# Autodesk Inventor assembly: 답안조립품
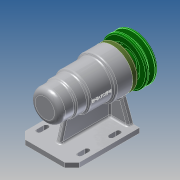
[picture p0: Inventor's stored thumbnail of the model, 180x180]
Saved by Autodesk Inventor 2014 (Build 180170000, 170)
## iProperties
Created: 2017-09
Part Number: 답안조립품
Document SubType Name: Assembly
Designer: kb542-22
Author: kb542-22
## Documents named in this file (12)
- C:\Users\kb542-22\Desktop\470907V1021\답안조립품.iam
- C:\Users\kb542-22\Desktop\470907V1021\1-본체.ipt
- C:\Users\kb542-22\Desktop\470907V1021\축.ipt
- C:\Users\kb542-22\Desktop\470907V1021\키 5 x 5 x 16.ipt
- C:\Users\kb542-22\Desktop\470907V1021\베어링 6004.ipt
- C:\Users\kb542-22\Desktop\470907V1021\V벨트풀리.ipt
- C:\Users\kb542-22\Desktop\470907V1021\멈춤나사 M3x8.ipt
- C:\Users\kb542-22\Desktop\470907V1021\어댑터슬리브.ipt
- C:\Users\kb542-22\Desktop\470907V1021\베어링 51202.ipt
- C:\Users\kb542-22\Desktop\470907V1021\볼트 M4 x 12.ipt
- C:\Users\kb542-22\Desktop\470907V1021\커버.ipt
- C:\Users\kb542-22\Desktop\470907V1021\오일 실 20x35x7.ipt
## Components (2 placed, 2 different names)
1. 1-본체:1
2. V벨트풀리:1
